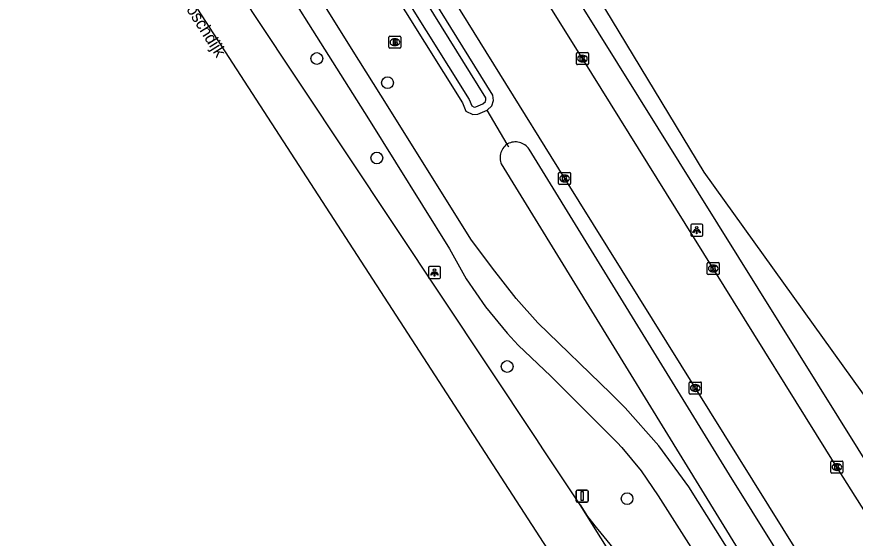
# Model space of a CAD drawing. Extents: x 158838 to 160074, y 386376 to 387776.
# Drawn here: x 159051.9 to 159121.6, y 386803.3 to 386846.6 of the extents above; entities that cross this region are included whole.
import ezdxf

# ---------------------------------------------------------------- set-up
doc = ezdxf.new("R2010")
doc.units = 0
for name, color, linetype in [('IMGEO_Berm_groen', 7, 'Continuous'), ('IMGEO_Boom', 7, 'Continuous'), ('IMGEO_Brandkraan', 7, 'Continuous'), ('IMGEO_Duiker', 7, 'Continuous'), ('IMGEO_Fietspad_gesloten', 7, 'Continuous'), ('IMGEO_Greppel_droge_sloot', 7, 'Continuous'), ('IMGEO_Kolk', 7, 'Continuous'), ('IMGEO_Lichtpunt', 7, 'Continuous'), ('IMGEO_Openbare_ruimte_label', 7, 'Continuous'), ('IMGEO_OVBaan_open', 7, 'Continuous'), ('IMGEO_Rijbaan_lokaal_open', 7, 'Continuous'), ('IMGEO_Rijbaan_regionaal_gesloten', 7, 'Continuous'), ('IMGEO_Verkeersbordpaal', 7, 'Continuous'), ('IMGEO_Voetpad_open', 7, 'Continuous'), ('IMGEO_Waterloop', 7, 'Continuous')]:
    doc.layers.add(name, color=color, linetype=linetype)

msp = doc.modelspace()

# ---------------------------------------------------------------- linework, layer by layer
at = {"layer": 'IMGEO_Berm_groen'}
for points in [[(159000, 386986.242), (158991.693, 386999.224), (158990.004, 386998.024), (159000, 386981.943), (159035.265, 386925.216), (159055.682, 386892.626), (159088.981, 386839.474), (159089.256, 386838.78), (159089.835, 386838.498), (159090.244, 386838.524), (159091.028, 386838.871), (159091.422, 386839.242), (159091.568, 386839.665), (159091.508, 386840.108), (159063.62, 386885.019), (159057.921, 386894.086), (159000, 386986.242)], [(159123.048, 386814.194), (159142.528, 386822.4), (159089.158, 386908.868), (159070.867, 386896.72), (159109.025, 386833.71), (159123.048, 386814.194)]]:
    msp.add_lwpolyline(points, dxfattribs=at)
at = {"layer": 'IMGEO_Boom'}
for centre in [(159076.875, 386843.159), (159082.751, 386841.147), (159081.861, 386834.9), (159092.693, 386817.576), (159102.66, 386806.6)]:
    msp.add_circle(centre, 0.489, dxfattribs=at)
at = {"layer": 'IMGEO_Brandkraan'}
for p, q in [((159082.859, 386844.091), (159082.859, 386844.943)), ((159082.934, 386845.017), (159083.786, 386845.017)), ((159083.347, 386844.797), (159083.372, 386844.797)), ((159083.86, 386844.943), (159083.86, 386844.091)), ((159083.786, 386844.017), (159082.934, 386844.017)), ((159083.37, 386844.237), (159083.345, 386844.237))]:
    msp.add_line(p, q, dxfattribs=at)
for points in [[(159082.859, 386844.091), (159082.859, 386844.943)], [(159082.934, 386845.017), (159083.786, 386845.017)], [(159083.207, 386844.717), (159083.207, 386844.317), (159083.42, 386844.317)], [(159083.438, 386844.717), (159083.207, 386844.717)], [(159083.386, 386844.636), (159083.332, 386844.636), (159083.332, 386844.56)], [(159083.86, 386844.943), (159083.86, 386844.091)], [(159083.786, 386844.017), (159082.934, 386844.017)], [(159083.332, 386844.56), (159083.385, 386844.56)], [(159083.394, 386844.484), (159083.332, 386844.484), (159083.332, 386844.403)], [(159083.332, 386844.403), (159083.394, 386844.403)]]:
    msp.add_lwpolyline(points, dxfattribs=at)
for centre, radius, start, end in [((159082.936, 386844.941), 0.0765, 91.55205, 178.44795), ((159082.936, 386844.941), 0.0765, 91.55205, 178.44795), ((159083.387, 386844.598), 0.0379, 267.82845, 90.93552), ((159083.442, 386844.572), 0.145, 59.4692, 91.53667), ((159083.467, 386844.619), 0.0922, 285.51372, 58.15012), ((159083.784, 386844.941), 0.0765, 1.55205, 88.44795), ((159083.784, 386844.941), 0.0765, 1.55205, 88.44795), ((159082.936, 386844.093), 0.0765, 181.55205, 268.44795), ((159082.936, 386844.093), 0.0765, 181.55205, 268.44795), ((159083.395, 386844.443), 0.0404, 269.87594, 90.50774), ((159083.426, 386844.568), 0.251, 268.66757, 293.53466), ((159083.472, 386844.427), 0.105, 301.31148, 78.98903), ((159083.784, 386844.093), 0.0765, 271.55205, 358.44795), ((159083.784, 386844.093), 0.0765, 271.55205, 358.44795)]:
    msp.add_arc(centre, radius, start, end, dxfattribs=at)
for centre, major_axis, ratio, start_param, end_param in [((159083.346, 386844.517), (-0.387, 0.002), 0.722429, 4.712389, 7.853982), ((159083.371, 386844.517), (-0.39, 0.002), 0.717154, 1.570796, 4.712389)]:
    msp.add_ellipse(centre, major_axis=major_axis, ratio=ratio, start_param=start_param, end_param=end_param, dxfattribs=at)
at = {"layer": 'IMGEO_Duiker'}
msp.add_lwpolyline([(159092.842, 386835.807), (159092.695, 386836.055), (159091.028, 386838.871)], dxfattribs=at)
at = {"layer": 'IMGEO_Fietspad_gesloten'}
for points in [[(159153.556, 386734.708), (159143.952, 386750), (159123.016, 386783.333), (159107.784, 386807.586), (159105.291, 386810.988), (159102.504, 386814.154), (159102.451, 386814.209), (159101.304, 386815.324), (159095.249, 386821.212), (159093.442, 386823.227), (159091.461, 386825.74), (159089.683, 386828.15), (159082.8, 386839.159), (159079.753, 386844.002), (159072.053, 386856.336), (159051.929, 386888.316), (159051.101, 386889.639), (159035.145, 386915.136), (159017.155, 386944.035), (159000, 386971.66), (158998.45, 386974.253), (158992.568, 386983.667), (158992.533, 386984.139), (158984.936, 386996.361)], [(158990.726, 386982.523), (158996.138, 386974.083), (159013.182, 386946.824), (159039.053, 386905.234), (159050.784, 386886.396), (159070.38, 386855.242), (159081.168, 386838.156), (159087.914, 386827.34), (159089.294, 386824.866), (159090.889, 386822.524), (159092.687, 386820.335), (159093.62, 386819.341), (159096.324, 386816.766), (159099.079, 386814.018), (159101.834, 386811.269), (159102.217, 386810.854), (159103.824, 386808.91), (159105.251, 386806.829), (159117.605, 386787.425)]]:
    msp.add_lwpolyline(points, dxfattribs=at)
at = {"layer": 'IMGEO_Greppel_droge_sloot'}
msp.add_lwpolyline([(158999.473, 386985.908), (158991.52, 386998.336), (158991.091, 386998.031), (158990.844, 386997.855), (159000.53, 386982.272), (159035.794, 386925.546), (159056.211, 386892.957), (159089.54, 386839.757), (159089.747, 386839.235), (159089.96, 386839.131), (159090.093, 386839.14), (159090.678, 386839.399), (159090.882, 386839.591), (159090.93, 386839.728), (159090.907, 386839.892), (159063.091, 386884.688), (159057.393, 386893.754), (158999.473, 386985.908)], dxfattribs=at)
at = {"layer": 'IMGEO_Kolk'}
for p, q in [((159098.452, 386842.724), (159098.452, 386843.576)), ((159098.527, 386843.65), (159099.379, 386843.65)), ((159098.94, 386843.43), (159098.965, 386843.43)), ((159099.453, 386843.576), (159099.453, 386842.724)), ((159099.379, 386842.65), (159098.527, 386842.65)), ((159098.963, 386842.87), (159098.938, 386842.87)), ((159096.969, 386832.772), (159096.969, 386833.624)), ((159097.044, 386833.698), (159097.896, 386833.698)), ((159097.457, 386833.478), (159097.482, 386833.478)), ((159097.97, 386833.624), (159097.97, 386832.772)), ((159097.48, 386832.918), (159097.455, 386832.918)), ((159097.896, 386832.698), (159097.044, 386832.698)), ((159109.323, 386825.289), (159109.323, 386826.141)), ((159109.398, 386826.215), (159110.25, 386826.215)), ((159109.811, 386825.995), (159109.836, 386825.995)), ((159110.324, 386826.141), (159110.324, 386825.289)), ((159110.25, 386825.215), (159109.398, 386825.215)), ((159109.834, 386825.435), (159109.809, 386825.435)), ((159107.829, 386815.365), (159107.829, 386816.217)), ((159107.904, 386816.291), (159108.756, 386816.291)), ((159108.317, 386816.071), (159108.342, 386816.071)), ((159108.83, 386816.217), (159108.83, 386815.365)), ((159108.34, 386815.511), (159108.315, 386815.511)), ((159108.756, 386815.291), (159107.904, 386815.291)), ((159119.596, 386808.801), (159119.596, 386809.653)), ((159119.671, 386809.727), (159120.523, 386809.727)), ((159120.084, 386809.507), (159120.109, 386809.507)), ((159120.597, 386809.653), (159120.597, 386808.801)), ((159120.523, 386808.727), (159119.671, 386808.727)), ((159120.107, 386808.947), (159120.082, 386808.947))]:
    msp.add_line(p, q, dxfattribs=at)
for points in [[(159098.452, 386842.724), (159098.452, 386843.576)], [(159098.527, 386843.65), (159099.379, 386843.65)], [(159098.773, 386843.35), (159098.896, 386843.35), (159098.896, 386843.199), (159099.026, 386843.35), (159099.19, 386843.35), (159099.044, 386843.199), (159099.197, 386842.95), (159099.045, 386842.95), (159098.96, 386843.114), (159098.896, 386843.047), (159098.896, 386842.95), (159098.773, 386842.95), (159098.773, 386843.35)], [(159099.453, 386843.576), (159099.453, 386842.724)], [(159099.379, 386842.65), (159098.527, 386842.65)], [(159096.969, 386832.772), (159096.969, 386833.624)], [(159097.044, 386833.698), (159097.896, 386833.698)], [(159097.97, 386833.624), (159097.97, 386832.772)], [(159097.29, 386833.398), (159097.413, 386833.398), (159097.413, 386833.247), (159097.543, 386833.398), (159097.707, 386833.398), (159097.561, 386833.247), (159097.714, 386832.998), (159097.562, 386832.998), (159097.477, 386833.162), (159097.413, 386833.095), (159097.413, 386832.998), (159097.29, 386832.998), (159097.29, 386833.398)], [(159097.896, 386832.698), (159097.044, 386832.698)], [(159109.323, 386825.289), (159109.323, 386826.141)], [(159109.398, 386826.215), (159110.25, 386826.215)], [(159109.644, 386825.915), (159109.767, 386825.915), (159109.767, 386825.764), (159109.897, 386825.915), (159110.061, 386825.915), (159109.915, 386825.764), (159110.068, 386825.515), (159109.916, 386825.515), (159109.831, 386825.679), (159109.767, 386825.612), (159109.767, 386825.515), (159109.644, 386825.515), (159109.644, 386825.915)], [(159110.324, 386826.141), (159110.324, 386825.289)], [(159110.25, 386825.215), (159109.398, 386825.215)], [(159107.829, 386815.365), (159107.829, 386816.217)], [(159107.904, 386816.291), (159108.756, 386816.291)], [(159108.83, 386816.217), (159108.83, 386815.365)], [(159108.15, 386815.991), (159108.273, 386815.991), (159108.273, 386815.84), (159108.403, 386815.991), (159108.567, 386815.991), (159108.421, 386815.84), (159108.574, 386815.591), (159108.422, 386815.591), (159108.337, 386815.755), (159108.273, 386815.688), (159108.273, 386815.591), (159108.15, 386815.591), (159108.15, 386815.991)], [(159108.756, 386815.291), (159107.904, 386815.291)], [(159119.596, 386808.801), (159119.596, 386809.653)], [(159119.671, 386809.727), (159120.523, 386809.727)], [(159119.917, 386809.427), (159120.04, 386809.427), (159120.04, 386809.276), (159120.17, 386809.427), (159120.334, 386809.427), (159120.188, 386809.276), (159120.341, 386809.027), (159120.189, 386809.027), (159120.104, 386809.191), (159120.04, 386809.124), (159120.04, 386809.027), (159119.917, 386809.027), (159119.917, 386809.427)], [(159120.597, 386809.653), (159120.597, 386808.801)], [(159120.523, 386808.727), (159119.671, 386808.727)]]:
    msp.add_lwpolyline(points, dxfattribs=at)
for centre, start, end in [((159098.529, 386843.574), 91.55205, 178.44795), ((159098.529, 386843.574), 91.55205, 178.44795), ((159099.377, 386843.574), 1.55205, 88.44795), ((159099.377, 386843.574), 1.55205, 88.44795), ((159098.529, 386842.726), 181.55205, 268.44795), ((159098.529, 386842.726), 181.55205, 268.44795), ((159099.377, 386842.726), 271.55205, 358.44795), ((159099.377, 386842.726), 271.55205, 358.44795), ((159097.046, 386833.622), 91.55205, 178.44795), ((159097.046, 386833.622), 91.55205, 178.44795), ((159097.894, 386833.622), 1.55205, 88.44795), ((159097.894, 386833.622), 1.55205, 88.44795), ((159097.046, 386832.774), 181.55205, 268.44795), ((159097.046, 386832.774), 181.55205, 268.44795), ((159097.894, 386832.774), 271.55205, 358.44795), ((159097.894, 386832.774), 271.55205, 358.44795), ((159109.4, 386826.139), 91.55205, 178.44795), ((159109.4, 386826.139), 91.55205, 178.44795), ((159110.248, 386826.139), 1.55205, 88.44795), ((159110.248, 386826.139), 1.55205, 88.44795), ((159109.4, 386825.291), 181.55205, 268.44795), ((159109.4, 386825.291), 181.55205, 268.44795), ((159110.248, 386825.291), 271.55205, 358.44795), ((159110.248, 386825.291), 271.55205, 358.44795), ((159107.906, 386816.215), 91.55205, 178.44795), ((159107.906, 386816.215), 91.55205, 178.44795), ((159108.754, 386816.215), 1.55205, 88.44795), ((159108.754, 386816.215), 1.55205, 88.44795), ((159107.906, 386815.367), 181.55205, 268.44795), ((159107.906, 386815.367), 181.55205, 268.44795), ((159108.754, 386815.367), 271.55205, 358.44795), ((159108.754, 386815.367), 271.55205, 358.44795), ((159119.673, 386809.651), 91.55205, 178.44795), ((159119.673, 386809.651), 91.55205, 178.44795), ((159120.521, 386809.651), 1.55205, 88.44795), ((159120.521, 386809.651), 1.55205, 88.44795), ((159119.673, 386808.803), 181.55205, 268.44795), ((159119.673, 386808.803), 181.55205, 268.44795), ((159120.521, 386808.803), 271.55205, 358.44795), ((159120.521, 386808.803), 271.55205, 358.44795)]:
    msp.add_arc(centre, 0.0765, start, end, dxfattribs=at)
for centre, major_axis, ratio, start_param, end_param in [((159098.939, 386843.15), (-0.387, 0.002), 0.722429, 4.712389, 7.853982), ((159098.964, 386843.15), (-0.39, 0.002), 0.717154, 1.570796, 4.712389), ((159097.456, 386833.198), (-0.387, 0.002), 0.722429, 4.712389, 7.853982), ((159097.481, 386833.198), (-0.39, 0.002), 0.717154, 1.570796, 4.712389), ((159109.81, 386825.715), (-0.387, 0.002), 0.722429, 4.712389, 7.853982), ((159109.835, 386825.715), (-0.39, 0.002), 0.717154, 1.570796, 4.712389), ((159108.316, 386815.791), (-0.387, 0.002), 0.722429, 4.712389, 7.853982), ((159108.341, 386815.791), (-0.39, 0.002), 0.717154, 1.570796, 4.712389), ((159120.083, 386809.227), (-0.387, 0.002), 0.722429, 4.712389, 7.853982), ((159120.108, 386809.227), (-0.39, 0.002), 0.717154, 1.570796, 4.712389)]:
    msp.add_ellipse(centre, major_axis=major_axis, ratio=ratio, start_param=start_param, end_param=end_param, dxfattribs=at)
at = {"layer": 'IMGEO_Lichtpunt'}
for p, q in [((159107.946, 386829.31), (159107.946, 386828.503)), ((159107.946, 386829.31), (159107.946, 386828.503)), ((159108.848, 386829.405), (159108.04, 386829.405)), ((159108.848, 386829.405), (159108.04, 386829.405)), ((159108.942, 386828.503), (159108.942, 386829.31)), ((159108.942, 386828.503), (159108.942, 386829.31)), ((159108.04, 386828.409), (159108.848, 386828.409)), ((159108.04, 386828.409), (159108.848, 386828.409)), ((159086.155, 386825.788), (159086.155, 386824.981)), ((159086.155, 386825.788), (159086.155, 386824.981)), ((159087.057, 386825.883), (159086.249, 386825.883)), ((159087.057, 386825.883), (159086.249, 386825.883)), ((159087.151, 386824.981), (159087.151, 386825.788)), ((159087.151, 386824.981), (159087.151, 386825.788)), ((159086.249, 386824.887), (159087.057, 386824.887)), ((159086.249, 386824.887), (159087.057, 386824.887))]:
    msp.add_line(p, q, dxfattribs=at)
for points in [[(159108.32, 386828.974), (159108.359, 386828.946), (159108.171, 386828.684), (159108.133, 386828.711), (159108.32, 386828.974)], [(159108.422, 386828.926), (159108.469, 386828.926), (159108.469, 386828.604), (159108.422, 386828.604), (159108.422, 386828.926)], [(159108.532, 386828.946), (159108.57, 386828.973), (159108.757, 386828.711), (159108.718, 386828.683), (159108.532, 386828.946)], [(159086.529, 386825.452), (159086.568, 386825.424), (159086.38, 386825.162), (159086.342, 386825.189), (159086.529, 386825.452)], [(159086.631, 386825.404), (159086.678, 386825.404), (159086.678, 386825.082), (159086.631, 386825.082), (159086.631, 386825.404)], [(159086.741, 386825.424), (159086.779, 386825.451), (159086.966, 386825.189), (159086.927, 386825.161), (159086.741, 386825.424)]]:
    msp.add_lwpolyline(points, dxfattribs=at)
for centre in [(159108.445, 386829.108), (159086.654, 386825.586)]:
    msp.add_circle(centre, 0.0994, dxfattribs=at)
for centre, start, end in [((159108.04, 386829.31), 90, 180), ((159108.04, 386829.31), 90, 180), ((159108.848, 386829.31), 0, 90), ((159108.848, 386829.31), 0, 90), ((159108.04, 386828.503), 180, 270), ((159108.04, 386828.503), 180, 270), ((159108.848, 386828.503), 270, 0), ((159108.848, 386828.503), 270, 360), ((159086.249, 386825.788), 90, 180), ((159086.249, 386825.788), 90, 180), ((159087.057, 386825.788), 0, 90), ((159087.057, 386825.788), 0, 90), ((159086.249, 386824.981), 180, 270), ((159086.249, 386824.981), 180, 270), ((159087.057, 386824.981), 270, 0), ((159087.057, 386824.981), 270, 360)]:
    msp.add_arc(centre, 0.0946, start, end, dxfattribs=at)
at = {"layer": 'IMGEO_OVBaan_open'}
for points in [[(159134, 386749.851), (159098.75, 386806.078)], [(159098.75, 386806.078), (159099.38, 386805.116), (159100.094, 386804.215), (159100.237, 386804.053), (159112.1, 386789.508), (159114.527, 386785.535)]]:
    msp.add_lwpolyline(points, dxfattribs=at)
at = {"layer": 'IMGEO_Rijbaan_lokaal_open'}
for points in [[(158992.734, 387001.043), (158993.387, 387000), (159000, 386989.439), (159000.316, 386988.934), (159010.09, 386973.23), (159021.504, 386954.997), (159031.839, 386938.426), (159043.257, 386920.182), (159053.024, 386904.489), (159059.057, 386894.827), (159065.997, 386883.711), (159075.251, 386868.876), (159086.653, 386850.613), (159097.471, 386833.198), (159108.33, 386815.791), (159119.183, 386798.375), (159120.937, 386795.51), (159121.337, 386794.968), (159121.784, 386794.465)], [(159123.327, 386804.096), (159120.096, 386809.226), (159109.823, 386825.714), (159098.952, 386843.149), (159088.091, 386860.551), (159077.264, 386877.959), (159073.44, 386884.112)]]:
    msp.add_lwpolyline(points, dxfattribs=at)
at = {"layer": 'IMGEO_Rijbaan_regionaal_gesloten'}
for points in [[(159143.031, 386728.393), (159114.787, 386773.529), (159063.769, 386852.239), (159047.794, 386877.825), (159027.337, 386910.591), (159001.844, 386951.425), (158973.435, 386996.928), (158951.308, 387032.368), (158919.283, 387083.664), (158891.623, 387127.967), (158871.393, 387160.012), (158853.231, 387189.196)], [(159098.75, 386806.078), (159095.71, 386810.659), (159095.09, 386811.591), (159071.557, 386846.971), (159064.463, 386858.196), (159063.391, 386859.93), (159061.455, 386863.013), (159048.457, 386883.647), (159034.701, 386905.543), (159017.299, 386933.828), (159009.693, 386945.652)]]:
    msp.add_lwpolyline(points, dxfattribs=at)
at = {"layer": 'IMGEO_Verkeersbordpaal'}
for p, q in [((159098.433, 386806.416), (159098.433, 386807.216)), ((159098.433, 386807.216), (159098.433, 386806.416)), ((159098.533, 386807.316), (159099.323, 386807.316)), ((159099.323, 386807.316), (159098.533, 386807.316)), ((159099.423, 386807.216), (159099.423, 386806.416)), ((159099.423, 386806.416), (159099.423, 386807.216)), ((159099.323, 386806.316), (159098.533, 386806.316)), ((159098.533, 386806.316), (159099.323, 386806.316))]:
    msp.add_line(p, q, dxfattribs=at)
msp.add_lwpolyline([(159098.853, 386807.191), (159099.003, 386807.191), (159099.003, 386806.441), (159098.853, 386806.441), (159098.853, 386807.191)], dxfattribs=at)
for centre, start, end in [((159098.533, 386807.216), 90, 180), ((159098.533, 386807.216), 90, 180), ((159099.323, 386807.216), 0, 90), ((159099.323, 386807.216), 360, 90), ((159098.533, 386806.416), 180, 270), ((159098.533, 386806.416), 180, 270), ((159099.323, 386806.416), 270, 0), ((159099.323, 386806.416), 270, 0)]:
    msp.add_arc(centre, 0.1, start, end, dxfattribs=at)
at = {"layer": 'IMGEO_Voetpad_open'}
msp.add_lwpolyline([(159125.228, 386805.37), (159075.363, 386885.31), (159076.413, 386885.966), (159067.552, 386900.158)], dxfattribs=at)
at = {"layer": 'IMGEO_Waterloop'}
msp.add_lwpolyline([(159125.822, 386785.104), (159111.158, 386808.568), (159094.529, 386835.632), (159094.451, 386835.732), (159094.365, 386835.824), (159094.271, 386835.909), (159094.17, 386835.984), (159094.062, 386836.051), (159093.949, 386836.107), (159093.832, 386836.153), (159093.71, 386836.189), (159093.586, 386836.213), (159093.461, 386836.227), (159093.334, 386836.229), (159093.208, 386836.219), (159093.083, 386836.199), (159092.961, 386836.167), (159092.842, 386836.125), (159092.727, 386836.072), (159092.695, 386836.055), (159092.596, 386835.977), (159092.504, 386835.891), (159092.42, 386835.797), (159092.345, 386835.695), (159092.279, 386835.588), (159092.224, 386835.475), (159092.178, 386835.357), (159092.143, 386835.236), (159092.119, 386835.112), (159092.107, 386834.986), (159092.105, 386834.86), (159092.115, 386834.735), (159092.136, 386834.61), (159092.168, 386834.488), (159092.196, 386834.408), (159114.93, 386797.418)], dxfattribs=at)

# ---------------------------------------------------------------- texts
at = {"layer": 'IMGEO_Openbare_ruimte_label'}
msp.add_text('Boschdijk', height=1, rotation=302.05394, dxfattribs=at).set_placement((159065.517, 386848.018))

doc.saveas('drawing.dxf')
